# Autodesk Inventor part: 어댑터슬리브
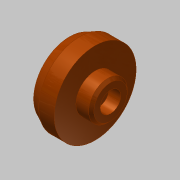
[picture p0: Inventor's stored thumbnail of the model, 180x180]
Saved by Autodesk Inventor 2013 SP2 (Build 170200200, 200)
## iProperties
Created: 2016-06
Part Number: 어댑터슬리브
Material: 강철, 탄소
Document SubType Name: Modeling
Designer: mduedu
Density: 7.87 g/cm^3
Author: mduedu
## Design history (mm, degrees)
sketch "스케치2"
  geometry: L1 (0, 0)-(0, 14); L2 (0, 14)-(-4, 16); L3 (-4, 16)-(-10, 16); L4 (-10, 16)-(-10, 7.5); L5 (-10, 7.5)-(-16, 7.5); L6 (-16, 7.5)-(-16, 0); L7 (-16, 0)-(0, 0)
  constraints: 14 end point, 4 parallel, 1 perpendicular, 1 vertical
  dimensions: "d0" = 32 diameter of L3 L7; "d2" = 28 diameter of L1.end L7; "d3" = 6 distance of L2.end L3.end; "d4" = 6 distance of L4.end L5.end; "d5" = 15 diameter of L5 L7; "d6" = 16 distance between parallel lines of L6 L1
revolve "회전1" sketch "스케치2" stored, may be unused: angle "d7" = 90 deg
sketch "스케치3"
  geometry: L1 (-16, -7.5)-(-16, 7.5) reference; L2 (-16, 7.5)-(-10, 7.5) reference; L3 (-10, 7.5)-(-10, 16) reference; L4 (-10, 16)-(-4, 16) reference; L5 (-4, 16)-(0, 14) reference; L6 (0, 14)-(0, -14) reference; L7 (0, -14)-(-4, -16) reference; L8 (-4, -16)-(-10, -16) reference; L9 (-10, -16)-(-10, -7.5) reference; L10 (-10, -7.5)-(-16, -7.5) reference; L11 (0, 10)-(-5, 10); L12 (-5, 10)-(-5, 8); L13 (-5, 8)-(-7, 6); L14 (-7, 6)-(-7, 0); L15 (-7, 0)-(0, 0); L16 (0, 10)-(0, 0)
  constraints: 12 end point, 3 parallel, 2 perpendicular, 1 point on line
  dimensions: "d8" = 20 diameter of L11 L15; "d10" = 16 diameter of L12.end L15; "d11" = 12 diameter of L13.end L15; "d12" = 9 distance between parallel lines of L14 L1; "d13" = 2 distance between parallel lines of L12 L14
revolve "회전2" sketch "스케치3" stored, may be unused: angle "d14" = 90 deg
chamfer "모따기1" distance "d15" = 1; stored, may be unused: second distance "d16" = 2, angle "d17" = 45 deg
sketch "스케치4"
  geometry: 2 further points
  constraints: 1 coincident
sketch "스케치5"
  geometry: 1 further point
hole "구멍1" sketch "스케치5" at (0, 0) diameter "d18" = 4.5; stored, may be unused: countersink angle "d22" = 90 deg, drill point angle "d24" = 0 deg; dims "d19" = 6, "d20" = 8, "d21" = 4.6, "d23" = 8
node "솔리드1"
node "절단 모서리 투영1"
